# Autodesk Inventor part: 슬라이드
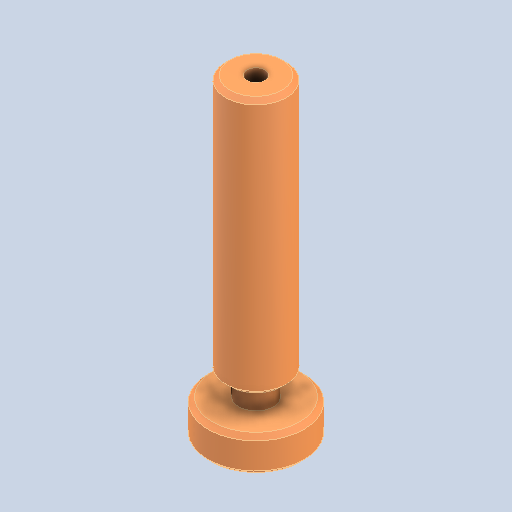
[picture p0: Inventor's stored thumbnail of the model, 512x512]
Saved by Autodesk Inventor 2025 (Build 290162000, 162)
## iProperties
Created: 2024-07
Part Number: 슬라이드
Material: 강철, 연강
Document SubType Name: Modeling
Designer: Administrator
Density: 7.86 g/cm^3
Appearance: 기본값
Author: jhkim
Sending System: Autodesk Inventor 2025
Preprocessor: ST-DEVELOPER v20
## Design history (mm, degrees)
feature "솔리드1"
node "솔리드2"
